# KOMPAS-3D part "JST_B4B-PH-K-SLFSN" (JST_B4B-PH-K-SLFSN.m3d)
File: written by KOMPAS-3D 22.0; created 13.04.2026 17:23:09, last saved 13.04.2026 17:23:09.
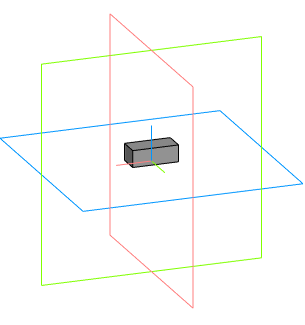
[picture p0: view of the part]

Document properties: Автор: Andrey; Полное имя файла: C:\Users\User1\Documents\JST_B4B-PH-K-SLFSN.m3d

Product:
- Part/product: JST_B4B-PH-K-SLFSN
    Комментарий: JST_B4B-PH-K-SLFSN

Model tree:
1. Операция без истории:1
